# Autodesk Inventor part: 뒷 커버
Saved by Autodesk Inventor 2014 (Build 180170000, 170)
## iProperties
Created: 2026-06
Part Number: 뒷 커버
Material: 일반
Document SubType Name: Modeling
Designer: dg
Density: 1 g/cm^3
Appearance: 기본값
Author: dg
Author: jhkim
Creation Date: 2026-05-29
Sending System: Autodesk Inventor 2027
Preprocessor: ST-DEVELOPER v20.1
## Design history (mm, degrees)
node "뒷 커버1"
node "솔리드1"
node "기준1"
